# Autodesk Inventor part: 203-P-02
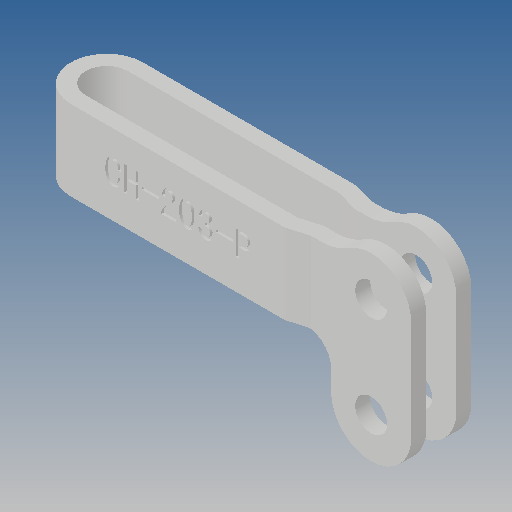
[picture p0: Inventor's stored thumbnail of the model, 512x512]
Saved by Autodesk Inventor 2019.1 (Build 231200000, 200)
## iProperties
Created: 2015-08
Part Number: 203-P-02
Material: Ogólny
Document SubType Name: Modeling
Designer: CADENGINEERING4
Density: 1 g/cm^3
Appearance: Domyślna
Author: CADENGINEERING4
Revision Number: ÈÎºÎ
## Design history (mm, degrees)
feature "ÇÐ³ý-À­Éì4"
node "Bryła1"
